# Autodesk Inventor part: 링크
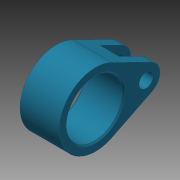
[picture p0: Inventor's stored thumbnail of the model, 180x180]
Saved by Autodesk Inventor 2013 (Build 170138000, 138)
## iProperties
Created: 2016-02
Part Number: 링크
Material: 강철, 연강
Document SubType Name: Modeling
Designer: test
Density: 1 g/cm^3
Author: test
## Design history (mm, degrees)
sketch "스케치1"
  geometry: L1 (20.222, 4.479)-(5.778, 11.645); L2 (20.222, -4.479)-(5.778, -11.645); A1 r 13 centre (0, 0) between (5.778, 11.645) and (5.778, -11.645); A2 r 5 centre (18, 0) between (20.222, -4.479) and (20.222, 4.479); 1 further point
  constraints: 4 end point, 4 point on circle, 4 tangent, 2 centre point, 1 coincident, 1 horizontal alignment
  dimensions: "d0" = 18 distance of point (0, 0) A2.centre; "d1" = 13 radius of A1; "d2" = 5 radius of A2
extrude "돌출1" new body sketch "스케치1" stored distance "d3" = 14; taper "d4" = 0 deg
sketch "스케치2"
  geometry: C1 r 10 at (0, 0); 1 further point
  constraints: 1 centre point, 1 coincident
  dimensions: "d5" = 20 diameter of C1
extrude "돌출2" cut sketch "스케치2" stored distance "d6" = 14; taper "d7" = 0 deg
sketch "스케치3"
  geometry: C1 r 2.5 at (18, 0); A1 r 5 centre (18, 0) between (20.222, -4.479) and (20.222, 4.479) reference; 1 further point
  constraints: 1 centre point, 1 coincident
  dimensions: "d8" = 5 diameter of C1
extrude "돌출3" cut sketch "스케치3" stored distance "d9" = 14; taper "d10" = 0 deg
sketch "스케치4"
  geometry: L1 (20.222, -4.479)-(5.778, -11.645) reference; L2 (5.778, 11.645)-(20.222, 4.479) reference; L3 (12, 8.558)-(12, -8.558); C1 r 2.5 at (18, 0) reference; C2 r 10 at (0, 0) reference; A1 r 13 centre (0, 0) between (5.778, 11.645) and (5.778, -11.645) reference; A2 r 5 centre (18, 0) between (20.222, -4.479) and (20.222, 4.479) reference; 1 further point
  constraints: 2 end point, 2 point on line, 1 vertical
  dimensions: "d11" = 12 distance from line of L3 point (0, 0)
extrude "돌출4" cut sketch "스케치4" stored distance "d12" = 7; taper "d13" = 0 deg
chamfer "모따기1" distance "d14" = 0.5; stored, may be unused: second distance "d15" = 2, angle "d16" = 45 deg
node "솔리드1"
node "절단 모서리 투영1"
